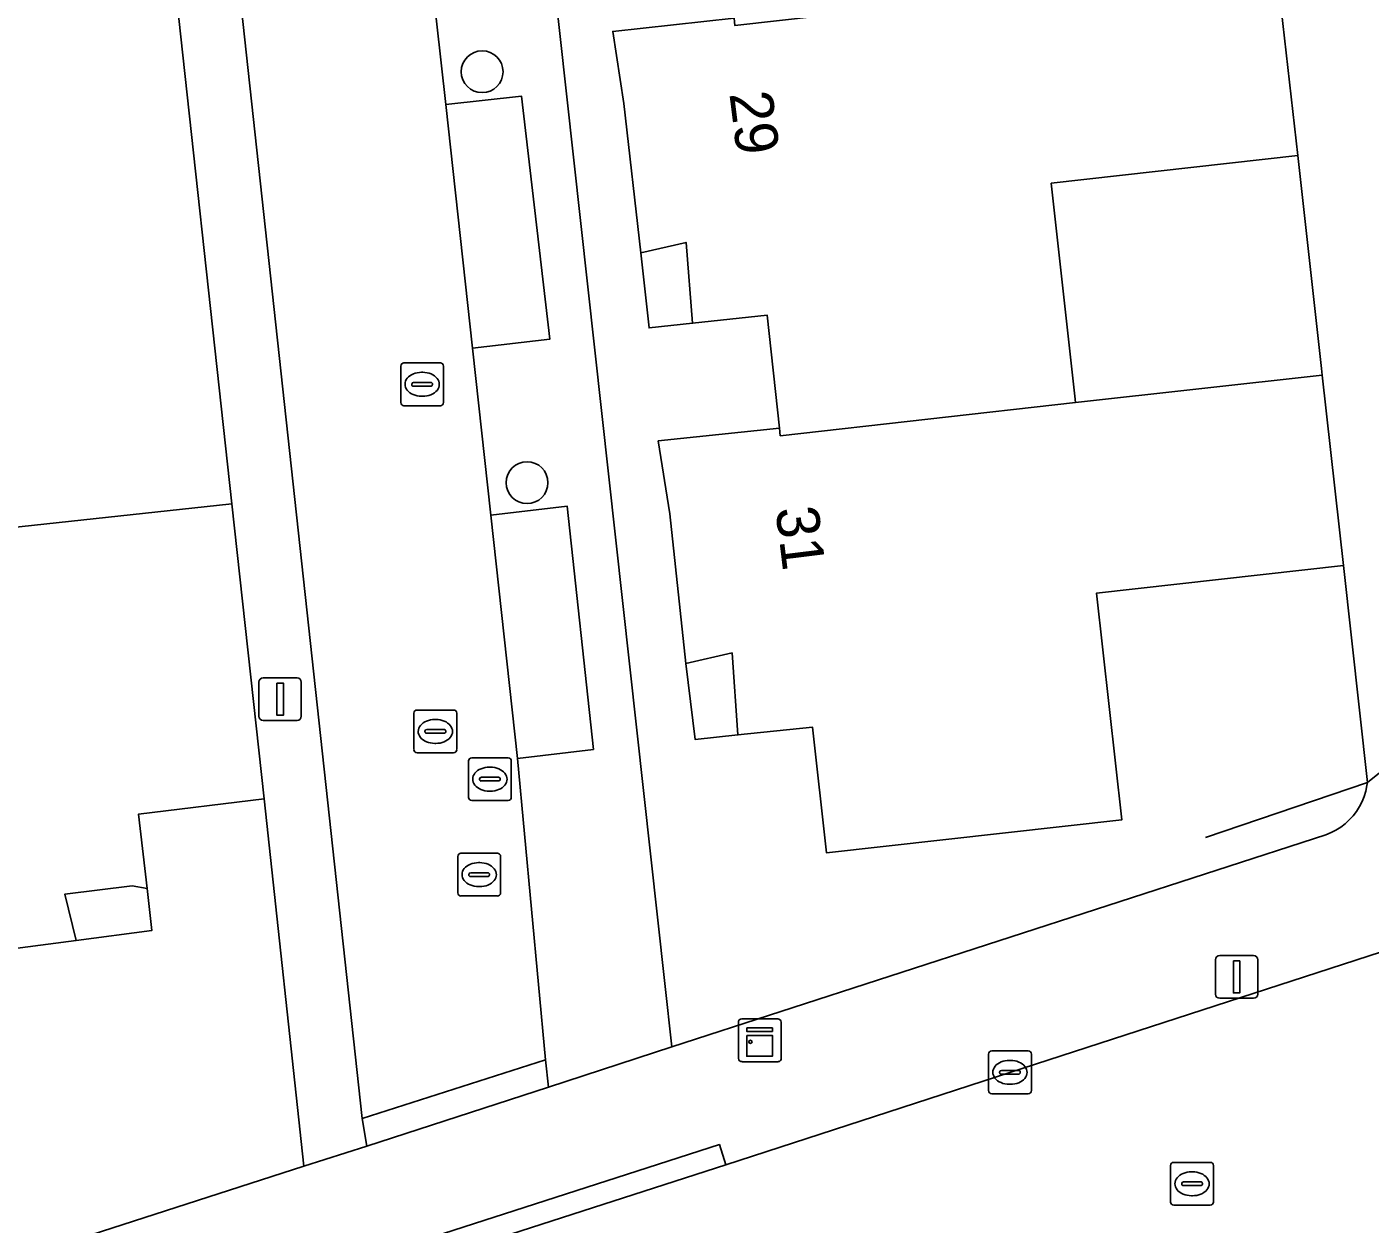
# Model space of a CAD drawing. Extents: x 161248 to 161848, y 384871 to 385383.
# Drawn here: x 161394.3 to 161425.69, y 385063.14 to 385091.12 of the extents above; entities that cross this region are included whole.
import ezdxf

# ---------------------------------------------------------------- set-up
doc = ezdxf.new("R2010")
doc.units = 0
for name, color, linetype in [('IMGEO_Boom', 7, 'Continuous'), ('IMGEO_Erf', 7, 'Continuous'), ('IMGEO_Kast', 7, 'Continuous'), ('IMGEO_Kolk', 7, 'Continuous'), ('IMGEO_Lichtmast', 7, 'Continuous'), ('IMGEO_Muur', 7, 'Continuous'), ('IMGEO_Pand', 7, 'Continuous'), ('IMGEO_Pand_nummerreeks', 7, 'Continuous'), ('IMGEO_Pand_overbouw', 7, 'Continuous'), ('IMGEO_Parkeervlak_open', 7, 'Continuous'), ('IMGEO_Rijbaan_lokaal_open', 7, 'Continuous'), ('IMGEO_Rioolput', 7, 'Continuous'), ('IMGEO_Voetpad_open', 7, 'Continuous')]:
    doc.layers.add(name, color=color, linetype=linetype)

msp = doc.modelspace()

# ---------------------------------------------------------------- linework, layer by layer
at = {"layer": 'IMGEO_Boom'}
for centre in [(161404.938, 385090.069), (161405.987, 385080.467)]:
    msp.add_circle(centre, 0.489, dxfattribs=at)
at = {"layer": 'IMGEO_Erf'}
for points in [[(161404.29, 385113.233), (161409.372, 385067.287), (161424.656, 385072.241), (161424.778, 385072.29), (161424.894, 385072.349), (161425.005, 385072.419), (161425.11, 385072.498), (161425.206, 385072.586), (161425.295, 385072.683), (161425.375, 385072.787), (161425.444, 385072.898), (161425.504, 385073.014), (161425.553, 385073.136), (161425.591, 385073.261), (161425.618, 385073.389), (161425.628, 385073.461), (161425.068, 385078.533), (161419.298, 385077.887), (161419.886, 385072.587), (161412.983, 385071.822), (161412.662, 385074.751), (161410.915, 385074.572), (161410.779, 385076.49), (161409.701, 385076.239), (161409.323, 385079.741), (161409.055, 385081.442), (161411.889, 385081.739), (161411.603, 385084.379), (161409.855, 385084.191), (161409.703, 385086.082), (161408.643, 385085.841), (161408.252, 385089.325), (161407.992, 385091.011), (161410.827, 385091.323)], [(161357.211, 385050.442), (161400.77, 385064.501), (161399.84, 385073.078), (161396.909, 385072.725), (161397.105, 385070.988), (161396.756, 385071.044), (161395.185, 385070.855), (161395.445, 385069.768), (161391.989, 385069.316)]]:
    msp.add_lwpolyline(points, dxfattribs=at)
for points in [[(161397.643, 385093.177), (161392.383, 385092.607), (161393.106, 385086.007), (161393.83, 385079.404), (161399.089, 385079.976)], [(161424.001, 385088.115), (161418.238, 385087.463), (161418.789, 385082.49), (161418.806, 385082.337), (161424.57, 385082.983), (161424.553, 385083.136)]]:
    msp.add_lwpolyline(points, close=True, dxfattribs=at)
at = {"layer": 'IMGEO_Kast'}
for p, q in [((161410.929, 385067.014), (161410.929, 385067.855)), ((161410.929, 385067.855), (161410.929, 385067.014)), ((161411.004, 385067.939), (161411.845, 385067.939)), ((161411.845, 385067.939), (161411.004, 385067.939)), ((161411.929, 385067.864), (161411.929, 385067.023)), ((161411.929, 385067.023), (161411.929, 385067.864)), ((161411.854, 385066.939), (161411.013, 385066.939)), ((161411.013, 385066.939), (161411.854, 385066.939))]:
    msp.add_line(p, q, dxfattribs=at)
for points in [[(161411.124, 385067.729), (161411.724, 385067.729), (161411.724, 385067.644), (161411.124, 385067.644), (161411.124, 385067.729)], [(161411.124, 385067.554), (161411.724, 385067.554), (161411.724, 385067.065), (161411.124, 385067.065), (161411.124, 385067.554)]]:
    msp.add_lwpolyline(points, dxfattribs=at)
msp.add_circle((161411.208, 385067.403), 0.0377, dxfattribs=at)
for centre, start, end in [((161411.007, 385067.861), 92.4484, 184.2845), ((161411.007, 385067.861), 92.4484, 184.2845), ((161411.851, 385067.861), 2.4484, 94.2845), ((161411.851, 385067.861), 2.4484, 94.2845), ((161411.007, 385067.017), 182.4484, 274.2845), ((161411.007, 385067.017), 182.4484, 274.2845), ((161411.851, 385067.017), 272.4484, 4.2845), ((161411.851, 385067.017), 272.4484, 4.2845)]:
    msp.add_arc(centre, 0.0779, start, end, dxfattribs=at)
at = {"layer": 'IMGEO_Kolk'}
for p, q in [((161403.11, 385083.266), (161403.962, 385083.266)), ((161403.035, 385082.34), (161403.035, 385083.192)), ((161403.523, 385083.046), (161403.548, 385083.046)), ((161404.036, 385083.192), (161404.036, 385082.34)), ((161403.294, 385082.76), (161403.294, 385082.772)), ((161403.732, 385082.723), (161403.334, 385082.723)), ((161403.337, 385082.809), (161403.735, 385082.809)), ((161403.778, 385082.772), (161403.778, 385082.76)), ((161403.962, 385082.266), (161403.11, 385082.266)), ((161403.546, 385082.486), (161403.521, 385082.486)), ((161404.368, 385070.884), (161404.368, 385071.736)), ((161404.443, 385071.81), (161405.295, 385071.81)), ((161404.856, 385071.59), (161404.881, 385071.59)), ((161405.369, 385071.736), (161405.369, 385070.884)), ((161404.627, 385071.304), (161404.627, 385071.316)), ((161404.67, 385071.353), (161405.068, 385071.353)), ((161405.111, 385071.316), (161405.111, 385071.304)), ((161405.065, 385071.267), (161404.667, 385071.267)), ((161404.879, 385071.03), (161404.854, 385071.03)), ((161405.295, 385070.81), (161404.443, 385070.81)), ((161416.773, 385066.264), (161416.773, 385067.116)), ((161416.848, 385067.19), (161417.7, 385067.19)), ((161417.261, 385066.97), (161417.286, 385066.97)), ((161417.774, 385067.116), (161417.774, 385066.264)), ((161417.032, 385066.684), (161417.032, 385066.696)), ((161417.47, 385066.647), (161417.072, 385066.647)), ((161417.075, 385066.733), (161417.473, 385066.733)), ((161417.516, 385066.696), (161417.516, 385066.684)), ((161417.284, 385066.41), (161417.259, 385066.41)), ((161417.7, 385066.19), (161416.848, 385066.19))]:
    msp.add_line(p, q, dxfattribs=at)
for points in [[(161403.11, 385083.266), (161403.962, 385083.266)], [(161403.035, 385082.34), (161403.035, 385083.192)], [(161404.036, 385083.192), (161404.036, 385082.34)], [(161403.962, 385082.266), (161403.11, 385082.266)], [(161404.368, 385070.884), (161404.368, 385071.736)], [(161404.443, 385071.81), (161405.295, 385071.81)], [(161405.369, 385071.736), (161405.369, 385070.884)], [(161405.295, 385070.81), (161404.443, 385070.81)], [(161416.773, 385066.264), (161416.773, 385067.116)], [(161416.848, 385067.19), (161417.7, 385067.19)], [(161417.774, 385067.116), (161417.774, 385066.264)], [(161417.7, 385066.19), (161416.848, 385066.19)]]:
    msp.add_lwpolyline(points, dxfattribs=at)
for centre, radius, start, end in [((161403.112, 385083.19), 0.0765, 91.552, 178.448), ((161403.112, 385083.19), 0.0765, 91.552, 178.448), ((161403.96, 385083.19), 0.0765, 1.552, 88.448), ((161403.96, 385083.19), 0.0765, 1.552, 88.448), ((161403.334, 385082.769), 0.0403, 85.8775, 175.7526), ((161403.331, 385082.759), 0.0366, 178.938, 274.7102), ((161403.735, 385082.766), 0.043, 264.8664, 352.4533), ((161403.739, 385082.771), 0.0386, 1.7309, 96.639), ((161403.112, 385082.342), 0.0765, 181.552, 268.448), ((161403.112, 385082.342), 0.0765, 181.552, 268.448), ((161403.96, 385082.342), 0.0765, 271.552, 358.448), ((161403.96, 385082.342), 0.0765, 271.552, 358.448), ((161404.445, 385071.734), 0.0765, 91.552, 178.448), ((161404.445, 385071.734), 0.0765, 91.552, 178.448), ((161405.293, 385071.734), 0.0765, 1.552, 88.448), ((161405.293, 385071.734), 0.0765, 1.552, 88.448), ((161404.667, 385071.313), 0.0403, 85.8775, 175.7526), ((161404.664, 385071.303), 0.0366, 178.938, 274.7102), ((161405.068, 385071.31), 0.043, 264.8664, 352.4533), ((161405.072, 385071.315), 0.0386, 1.7309, 96.639), ((161404.445, 385070.886), 0.0765, 181.552, 268.448), ((161404.445, 385070.886), 0.0765, 181.552, 268.448), ((161405.293, 385070.886), 0.0765, 271.552, 358.448), ((161405.293, 385070.886), 0.0765, 271.552, 358.448), ((161416.85, 385067.114), 0.0765, 91.552, 178.448), ((161416.85, 385067.114), 0.0765, 91.552, 178.448), ((161417.698, 385067.114), 0.0765, 1.552, 88.448), ((161417.698, 385067.114), 0.0765, 1.552, 88.448), ((161417.072, 385066.693), 0.0403, 85.8775, 175.7526), ((161417.069, 385066.683), 0.0366, 178.938, 274.7102), ((161417.473, 385066.69), 0.043, 264.8664, 352.4533), ((161417.477, 385066.695), 0.0386, 1.7309, 96.639), ((161416.85, 385066.266), 0.0765, 181.552, 268.448), ((161416.85, 385066.266), 0.0765, 181.552, 268.448), ((161417.698, 385066.266), 0.0765, 271.552, 358.448), ((161417.698, 385066.266), 0.0765, 271.552, 358.448)]:
    msp.add_arc(centre, radius, start, end, dxfattribs=at)
for centre, major_axis, ratio, start_param, end_param in [((161403.522, 385082.766), (-0.387, 0.002), 0.722429, 4.712389, 7.853982), ((161403.547, 385082.766), (-0.39, 0.002), 0.717154, 1.570796, 4.712389), ((161404.855, 385071.31), (-0.387, 0.002), 0.722429, 4.712389, 7.853982), ((161404.88, 385071.31), (-0.39, 0.002), 0.717154, 1.570796, 4.712389), ((161417.26, 385066.69), (-0.387, 0.002), 0.722429, 4.712389, 7.853982), ((161417.285, 385066.69), (-0.39, 0.002), 0.717154, 1.570796, 4.712389)]:
    msp.add_ellipse(centre, major_axis=major_axis, ratio=ratio, start_param=start_param, end_param=end_param, dxfattribs=at)
at = {"layer": 'IMGEO_Lichtmast'}
for p, q in [((161399.721, 385075.009), (161399.721, 385075.809)), ((161399.721, 385075.809), (161399.721, 385075.009)), ((161399.821, 385075.909), (161400.611, 385075.909)), ((161400.611, 385075.909), (161399.821, 385075.909)), ((161400.711, 385075.809), (161400.711, 385075.009)), ((161400.711, 385075.009), (161400.711, 385075.809)), ((161400.611, 385074.909), (161399.821, 385074.909)), ((161399.821, 385074.909), (161400.611, 385074.909)), ((161422.176, 385069.419), (161422.966, 385069.419)), ((161422.966, 385069.419), (161422.176, 385069.419)), ((161422.076, 385068.519), (161422.076, 385069.319)), ((161422.076, 385069.319), (161422.076, 385068.519)), ((161423.066, 385069.319), (161423.066, 385068.519)), ((161423.066, 385068.519), (161423.066, 385069.319)), ((161422.966, 385068.419), (161422.176, 385068.419)), ((161422.176, 385068.419), (161422.966, 385068.419))]:
    msp.add_line(p, q, dxfattribs=at)
for points in [[(161400.141, 385075.784), (161400.291, 385075.784), (161400.291, 385075.034), (161400.141, 385075.034), (161400.141, 385075.784)], [(161422.496, 385069.294), (161422.646, 385069.294), (161422.646, 385068.544), (161422.496, 385068.544), (161422.496, 385069.294)]]:
    msp.add_lwpolyline(points, dxfattribs=at)
for centre, start, end in [((161399.821, 385075.809), 90, 180), ((161399.821, 385075.809), 90, 180), ((161400.611, 385075.809), 0, 90), ((161400.611, 385075.809), 360, 90), ((161399.821, 385075.009), 180, 270), ((161399.821, 385075.009), 180, 270), ((161400.611, 385075.009), 270, 0), ((161400.611, 385075.009), 270, 0), ((161422.176, 385069.319), 90, 180), ((161422.176, 385069.319), 90, 180), ((161422.966, 385069.319), 0, 90), ((161422.966, 385069.319), 360, 90), ((161422.176, 385068.519), 180, 270), ((161422.176, 385068.519), 180, 270), ((161422.966, 385068.519), 270, 0), ((161422.966, 385068.519), 270, 0)]:
    msp.add_arc(centre, 0.1, start, end, dxfattribs=at)
at = {"layer": 'IMGEO_Muur'}
for points in [[(161424.553, 385083.136), (161424.001, 385088.115)], [(161425.628, 385073.461), (161425.068, 385078.533)], [(161421.841, 385072.176), (161425.628, 385073.461)]]:
    msp.add_lwpolyline(points, dxfattribs=at)
at = {"layer": 'IMGEO_Pand'}
for points in [[(161418.238, 385087.463), (161424.001, 385088.115), (161423.497, 385092.578), (161417.733, 385091.926), (161410.844, 385091.147), (161410.827, 385091.323), (161407.992, 385091.011), (161408.252, 385089.325), (161408.643, 385085.841), (161409.703, 385086.082), (161409.855, 385084.191), (161411.603, 385084.379), (161411.889, 385081.739), (161411.905, 385081.564), (161418.806, 385082.337), (161418.789, 385082.49)], [(161399.089, 385079.976), (161393.83, 385079.404), (161393.106, 385086.007), (161388.471, 385085.497), (161389.196, 385078.897), (161390.289, 385070.246), (161390.427, 385069.158), (161391.989, 385069.316), (161395.445, 385069.768), (161395.185, 385070.855), (161396.756, 385071.044), (161397.105, 385070.988), (161396.909, 385072.725), (161399.84, 385073.078)], [(161425.068, 385078.533), (161424.57, 385082.983), (161418.806, 385082.337), (161411.905, 385081.564), (161411.889, 385081.739), (161409.055, 385081.442), (161409.323, 385079.741), (161409.701, 385076.239), (161410.779, 385076.49), (161410.915, 385074.572), (161412.662, 385074.751), (161412.983, 385071.822), (161419.886, 385072.587), (161419.298, 385077.887)]]:
    msp.add_lwpolyline(points, close=True, dxfattribs=at)
at = {"layer": 'IMGEO_Pand_overbouw'}
for points in [[(161409.703, 385086.082), (161408.643, 385085.841), (161408.84, 385084.082), (161409.855, 385084.191)], [(161410.779, 385076.49), (161409.701, 385076.239), (161409.913, 385074.469), (161410.915, 385074.572)], [(161397.105, 385070.988), (161396.756, 385071.044), (161395.185, 385070.855), (161395.445, 385069.768), (161397.216, 385070)]]:
    msp.add_lwpolyline(points, close=True, dxfattribs=at)
at = {"layer": 'IMGEO_Parkeervlak_open'}
for points in [[(161404.713, 385083.613), (161406.517, 385083.819), (161405.86, 385089.497), (161404.091, 385089.305)], [(161405.765, 385074.022), (161407.538, 385074.234), (161406.924, 385079.919), (161405.141, 385079.709)]]:
    msp.add_lwpolyline(points, close=True, dxfattribs=at)
at = {"layer": 'IMGEO_Rijbaan_lokaal_open'}
for points in [[(161392.01, 385158.338), (161396.837, 385114.227), (161397.29, 385110.152), (161402.132, 385065.615), (161406.419, 385066.984), (161405.765, 385074.022), (161405.141, 385079.709), (161404.713, 385083.613), (161404.091, 385089.305), (161403.65, 385093.205), (161403.051, 385098.895), (161402.612, 385102.792), (161401.979, 385108.485), (161401.538, 385112.4), (161400.927, 385118.092), (161400.502, 385121.982), (161399.875, 385127.654), (161399.442, 385131.564), (161398.809, 385137.23), (161398.4, 385141.132), (161397.792, 385146.817), (161397.354, 385150.719), (161396.733, 385156.417), (161395.989, 385162.959)], [(161469.526, 385083.633), (161460.453, 385080.682), (161440.926, 385074.344), (161430.157, 385070.87), (161417.274, 385066.689), (161410.636, 385064.527), (161397.711, 385060.359), (161391.558, 385058.354), (161387.979, 385057.181), (161382.273, 385055.346), (161378.684, 385054.165), (161378.461, 385054.101), (161373.432, 385052.501), (161369.85, 385051.335), (161364.64, 385049.653), (161361.05, 385048.512), (161359.276, 385047.937), (161358.951, 385047.777), (161358.438, 385047.57), (161357.909, 385047.41), (161338.624, 385041.3)]]:
    msp.add_lwpolyline(points, dxfattribs=at)
msp.add_lwpolyline([(161402.132, 385065.615), (161402.239, 385064.962), (161406.487, 385066.347), (161406.419, 385066.984)], close=True, dxfattribs=at)
at = {"layer": 'IMGEO_Rioolput'}
for p, q in [((161403.343, 385074.229), (161403.343, 385075.081)), ((161403.418, 385075.155), (161404.27, 385075.155)), ((161404.344, 385075.081), (161404.344, 385074.229)), ((161403.831, 385074.935), (161403.856, 385074.935)), ((161403.602, 385074.649), (161403.602, 385074.661)), ((161404.04, 385074.612), (161403.642, 385074.612)), ((161403.645, 385074.698), (161404.043, 385074.698)), ((161404.086, 385074.661), (161404.086, 385074.649)), ((161404.27, 385074.155), (161403.418, 385074.155)), ((161403.854, 385074.375), (161403.829, 385074.375)), ((161404.618, 385073.114), (161404.618, 385073.966)), ((161404.693, 385074.04), (161405.545, 385074.04)), ((161405.106, 385073.82), (161405.131, 385073.82)), ((161405.619, 385073.966), (161405.619, 385073.114)), ((161404.877, 385073.534), (161404.877, 385073.546)), ((161405.315, 385073.497), (161404.917, 385073.497)), ((161404.92, 385073.583), (161405.318, 385073.583)), ((161405.361, 385073.546), (161405.361, 385073.534)), ((161405.129, 385073.26), (161405.104, 385073.26)), ((161405.545, 385073.04), (161404.693, 385073.04)), ((161421.029, 385063.66), (161421.029, 385064.512)), ((161421.104, 385064.586), (161421.956, 385064.586)), ((161422.03, 385064.512), (161422.03, 385063.66)), ((161421.288, 385064.08), (161421.288, 385064.092)), ((161421.331, 385064.129), (161421.729, 385064.129)), ((161421.517, 385064.366), (161421.542, 385064.366)), ((161421.772, 385064.092), (161421.772, 385064.08)), ((161421.726, 385064.043), (161421.328, 385064.043)), ((161421.54, 385063.806), (161421.515, 385063.806)), ((161421.956, 385063.586), (161421.104, 385063.586))]:
    msp.add_line(p, q, dxfattribs=at)
for points in [[(161403.343, 385074.229), (161403.343, 385075.081)], [(161403.418, 385075.155), (161404.27, 385075.155)], [(161404.344, 385075.081), (161404.344, 385074.229)], [(161404.27, 385074.155), (161403.418, 385074.155)], [(161404.618, 385073.114), (161404.618, 385073.966)], [(161404.693, 385074.04), (161405.545, 385074.04)], [(161405.619, 385073.966), (161405.619, 385073.114)], [(161405.545, 385073.04), (161404.693, 385073.04)], [(161421.029, 385063.66), (161421.029, 385064.512)], [(161421.104, 385064.586), (161421.956, 385064.586)], [(161422.03, 385064.512), (161422.03, 385063.66)], [(161421.956, 385063.586), (161421.104, 385063.586)]]:
    msp.add_lwpolyline(points, dxfattribs=at)
for centre, radius, start, end in [((161403.42, 385075.079), 0.0765, 91.552, 178.448), ((161403.42, 385075.079), 0.0765, 91.552, 178.448), ((161404.268, 385075.079), 0.0765, 1.552, 88.448), ((161404.268, 385075.079), 0.0765, 1.552, 88.448), ((161403.642, 385074.658), 0.0403, 85.8775, 175.7526), ((161403.639, 385074.648), 0.0366, 178.938, 274.7102), ((161404.043, 385074.655), 0.043, 264.8664, 352.4533), ((161404.047, 385074.66), 0.0386, 1.7309, 96.639), ((161403.42, 385074.231), 0.0765, 181.552, 268.448), ((161403.42, 385074.231), 0.0765, 181.552, 268.448), ((161404.268, 385074.231), 0.0765, 271.552, 358.448), ((161404.268, 385074.231), 0.0765, 271.552, 358.448), ((161404.695, 385073.964), 0.0765, 91.552, 178.448), ((161404.695, 385073.964), 0.0765, 91.552, 178.448), ((161405.543, 385073.964), 0.0765, 1.552, 88.448), ((161405.543, 385073.964), 0.0765, 1.552, 88.448), ((161404.917, 385073.543), 0.0403, 85.8775, 175.7526), ((161404.914, 385073.533), 0.0366, 178.938, 274.7102), ((161405.318, 385073.54), 0.043, 264.8664, 352.4533), ((161405.322, 385073.545), 0.0386, 1.7309, 96.639), ((161404.695, 385073.116), 0.0765, 181.552, 268.448), ((161404.695, 385073.116), 0.0765, 181.552, 268.448), ((161405.543, 385073.116), 0.0765, 271.552, 358.448), ((161405.543, 385073.116), 0.0765, 271.552, 358.448), ((161421.106, 385064.51), 0.0765, 91.552, 178.448), ((161421.106, 385064.51), 0.0765, 91.552, 178.448), ((161421.954, 385064.51), 0.0765, 1.552, 88.448), ((161421.954, 385064.51), 0.0765, 1.552, 88.448), ((161421.328, 385064.089), 0.0403, 85.8775, 175.7526), ((161421.325, 385064.079), 0.0366, 178.938, 274.7102), ((161421.729, 385064.086), 0.043, 264.8664, 352.4533), ((161421.733, 385064.091), 0.0386, 1.7309, 96.639), ((161421.106, 385063.662), 0.0765, 181.552, 268.448), ((161421.106, 385063.662), 0.0765, 181.552, 268.448), ((161421.954, 385063.662), 0.0765, 271.552, 358.448), ((161421.954, 385063.662), 0.0765, 271.552, 358.448)]:
    msp.add_arc(centre, radius, start, end, dxfattribs=at)
for centre, major_axis, ratio, start_param, end_param in [((161403.83, 385074.655), (-0.387, 0.002), 0.722429, 4.712389, 7.853982), ((161403.855, 385074.655), (-0.39, 0.002), 0.717154, 1.570796, 4.712389), ((161405.105, 385073.54), (-0.387, 0.002), 0.722429, 4.712389, 7.853982), ((161405.13, 385073.54), (-0.39, 0.002), 0.717154, 1.570796, 4.712389), ((161421.516, 385064.086), (-0.387, 0.002), 0.722429, 4.712389, 7.853982), ((161421.541, 385064.086), (-0.39, 0.002), 0.717154, 1.570796, 4.712389)]:
    msp.add_ellipse(centre, major_axis=major_axis, ratio=ratio, start_param=start_param, end_param=end_param, dxfattribs=at)
at = {"layer": 'IMGEO_Voetpad_open'}
for points in [[(161423.497, 385092.578), (161424.001, 385088.115), (161424.553, 385083.136), (161424.57, 385082.983), (161425.068, 385078.533), (161425.628, 385073.461), (161428.151, 385075.476), (161427.314, 385083.055), (161431.343, 385083.465), (161431.579, 385081.436), (161439.843, 385082.364), (161439.505, 385085.406), (161438.589, 385085.303), (161438.857, 385082.906), (161432.384, 385082.18), (161432.136, 385084.473), (161427.209, 385083.967), (161426.978, 385086.052), (161418.12, 385166.146)], [(161403.65, 385093.205), (161404.091, 385089.305), (161405.86, 385089.497), (161406.517, 385083.819), (161404.713, 385083.613), (161405.141, 385079.709), (161406.924, 385079.919), (161407.538, 385074.234), (161405.765, 385074.022), (161406.419, 385066.984), (161406.487, 385066.347), (161409.372, 385067.287), (161404.29, 385113.233)], [(161417.274, 385066.689), (161430.157, 385070.87), (161440.926, 385074.344), (161460.453, 385080.682), (161469.526, 385083.633)], [(161428.151, 385075.476), (161425.628, 385073.461), (161425.618, 385073.389), (161425.591, 385073.261), (161425.553, 385073.136), (161425.504, 385073.014), (161425.444, 385072.898), (161425.375, 385072.787), (161425.295, 385072.683), (161425.206, 385072.586), (161425.11, 385072.498), (161425.005, 385072.419), (161424.894, 385072.349), (161424.778, 385072.29), (161424.656, 385072.241), (161409.372, 385067.287), (161406.487, 385066.347), (161402.239, 385064.962), (161400.77, 385064.501), (161357.211, 385050.442)], [(161391.558, 385058.354), (161397.711, 385060.359), (161397.558, 385060.834), (161410.483, 385065.002), (161410.636, 385064.527), (161417.274, 385066.689)]]:
    msp.add_lwpolyline(points, dxfattribs=at)
for points in [[(161397.29, 385110.152), (161395.787, 385109.99), (161396.177, 385106.561), (161396.893, 385100.095), (161397.643, 385093.177), (161399.089, 385079.976), (161399.84, 385073.078), (161400.77, 385064.501), (161402.239, 385064.962), (161402.132, 385065.615)], [(161410.636, 385064.527), (161410.483, 385065.002), (161397.558, 385060.834), (161397.711, 385060.359)]]:
    msp.add_lwpolyline(points, close=True, dxfattribs=at)

# ---------------------------------------------------------------- texts
at = {"layer": 'IMGEO_Pand_nummerreeks'}
for s, rotation, p in [('29', 277.179, (161410.715, 385089.56)), ('31', 277.0758, (161411.791, 385079.859))]:
    msp.add_text(s, height=1, rotation=rotation, dxfattribs=at).set_placement(p)

doc.saveas('drawing.dxf')
